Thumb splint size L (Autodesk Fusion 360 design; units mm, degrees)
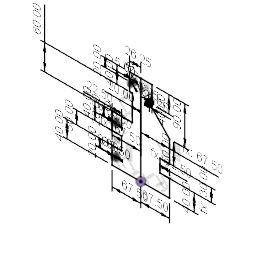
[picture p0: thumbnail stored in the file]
part number: 2025-11-24-13-59-10-673
sketch "Sketch1" plane through (0, 0, 0) normal (0, 1, 0) x axis (1, 0, 0)
  line L1 (-67.5, 0) -> (0, 0)
  line L2 (-67.5, -40) -> (-67.5, 0)
  line L3 (0, -210) -> (0, 0)
  line L4 (-45, -70) -> (-45, -40)
  line L5 (-67.5, -70) -> (-45, -70)
  line L6 (-67.5, -110) -> (-67.5, -70)
  line L7 (-20, -110) -> (-67.5, -110)
  line L8 (-20, -170) -> (-20, -110)
  line L9 (-26.25, -210) -> (-26.25, -170)
  line L10 (-26.25, -210) -> (0, -210)
  line L11 (26.25, -210) -> (0, -210)
  line L12 (26.25, -170) -> (26.25, -210)
  line L13 (67.5, -70) -> (67.5, -120)
  line L14 (67.5, 0) -> (0, 0)
  line L15 (67.5, -40) -> (67.5, 0)
  line L16 (-45, -40) -> (-67.5, -40)
  line L17 (45, -40) -> (67.5, -40)
  line L18 (45, -70) -> (45, -40)
  line L19 (67.5, -70) -> (45, -70)
  line L20 (-26.25, -170) -> (-20, -170)
  line L21 (67.5, -120) -> (20, -170)
  line L22 (20, -170) -> (26.25, -170)
  circle C1 centre (-59.5, -20) radius 1.75
  circle C2 centre (-59.5, -90) radius 1.75
  circle C3 centre (-21.25, -190) radius 1.75
  circle C4 centre (20, -170) radius 3.125
  point P1 (0, 0)
  point P2 (0, 0)
  point P6 (0, 0)
  point P20 (0, 0)
  point P3 (-67.5, 0)
  point P4 (-67.5, 0)
  point P28 (20, -170)
  point P29 (20, -170)
  point P5 (-67.5, -40)
  point P9 (-45, -40)
  point P10 (-45, -70)
  point P11 (-67.5, -70)
  point P12 (-67.5, -110)
  point P7 (0, -210)
  point P8 (-26.25, -210)
  point P16 (26.25, -210)
  point P17 (26.25, -170)
  point P15 (-26.25, -170)
  point P18 (67.5, -120)
  point P19 (67.5, -70)
  point P21 (67.5, 0)
  point P22 (67.5, -40)
  point P23 (45, -40)
  point P24 (45, -70)
  point P13 (-20, -110)
  point P14 (-20, -170)
  point P27 (-21.25, -190)
  point P26 (-59.5, -90)
  point P25 (-59.5, -20)
  coincident P1 P2
  coincident P1 P6
  perpendicular L1 L3
  vertical L4
  perpendicular L4 L5
  perpendicular L5 L6
  perpendicular L6 L7
  perpendicular L7 L8
  perpendicular L3 L10
  perpendicular L9 L10
  perpendicular L3 L11
  perpendicular L11 L12
  vertical L13
  coincident P1 P20
  perpendicular L3 L14
  perpendicular L14 L15
  perpendicular L2 L16
  perpendicular L15 L17
  perpendicular L18 L19
  perpendicular L13 L19
  coincident P3 P4
  perpendicular L1 L2
  perpendicular L8 L20
  perpendicular L4 L16
  perpendicular L12 L22
  coincident P28 P29
  dimension "d1" distance P2 P3 = 67.5 (= "( 135 / 2 ) * 1 mm")
  dimension "d2" distance P4 P5 = 40
  dimension "d4" distance P9 P10 = 30
  dimension "d7" distance P10 P11 = 22.5 (= "( ( 135 - 90 ) / 2 ) * 1 mm")
  dimension "d9" distance L3 P12 = 67.5 (= "d1")
  dimension "d10" distance P7 P8 = 26.25
  dimension "d11" distance P7 P16 = 26.25
  dimension "d12" distance P16 P17 = 40
  dimension "d13" distance P8 P15 = 40
  dimension "d14" distance L11 P18 = 90
  dimension "d15" distance L3 P18 = 67.5 (= "d1")
  dimension "d16" distance P18 P19 = 50
  dimension "d17" distance P20 P21 = 67.5
  dimension "d18" distance P21 P22 = 40
  dimension "d22" distance P23 P24 = 30 (= "d4")
  dimension "d23" distance L3 P13 = 20
  dimension "d44" distance P11 P12 = 40
  dimension "d45" distance P13 P14 = 60
  dimension "d46" diameter C1 = 3.5
  dimension "d47" diameter C2 = 3.5
  dimension "d48" diameter C3 = 3.5
  dimension "d49" distance L9 P27 = 5
  dimension "d50" distance L6 P26 = 8
  dimension "d51" distance L2 P25 = 8
  dimension "d52" distance L7 P26 = 20
  dimension "d53" distance L16 P25 = 20
  dimension "d54" distance L10 P27 = 20
  dimension "d67" distance P17 P28 = 6.25
  dimension "d74" distance P19 P24 = 22.5 (= "d7")
extrude "Extrude1" new body sketch "Sketch1" along normal blind 1.5
extrude "Extrude2" cut sketch "Sketch1" profile of C1 C2 C3 along normal blind 190.504
mirror "Mirror1" mirrorStitchTolerance 0.1
fillet "Fillet1" radius 10
fillet "Fillet2" radius 2
fillet "Fillet3" radius 10 10
fillet "Fillet4" radius 5
fillet "Fillet5" radius 25
fillet "Fillet7" radius 5 5
work_plane "WorkPlane1" AlongDistance -89.936
sketch "Sketch2" plane through (0, -89.936, 0) normal (0, 1, 0) x axis (1, 0, 0)
  line L1 (0, -210) -> (0, 0)
  circle C1 centre (-48, -13.48) radius 2
  circle C2 centre (-36, -13.48) radius 2
  circle C3 centre (-24, -13.48) radius 2
  circle C4 centre (-12, -13.48) radius 2
  circle C5 centre (0, -13.48) radius 2
  circle C6 centre (-48, -24.98) radius 2
  circle C7 centre (-36, -24.98) radius 2
  circle C8 centre (-24, -24.98) radius 2
  circle C9 centre (-12, -24.98) radius 2
  circle C10 centre (0, -24.98) radius 2
  circle C11 centre (-48, -36.48) radius 2
  circle C12 centre (-36, -36.48) radius 2
  circle C13 centre (-24, -36.48) radius 2
  circle C14 centre (-12, -36.48) radius 2
  circle C15 centre (0, -36.48) radius 2
  circle C16 centre (-48, -47.98) radius 2
  circle C17 centre (-36, -47.98) radius 2
  circle C18 centre (-24, -47.98) radius 2
  circle C19 centre (-12, -47.98) radius 2
  circle C20 centre (0, -47.98) radius 2
  circle C21 centre (12, -13.48) radius 2
  circle C22 centre (24, -13.48) radius 2
  circle C23 centre (36, -13.48) radius 2
  circle C24 centre (48, -13.48) radius 2
  circle C25 centre (12, -24.98) radius 2
  circle C26 centre (24, -24.98) radius 2
  circle C27 centre (36, -24.98) radius 2
  circle C28 centre (48, -24.98) radius 2
  circle C29 centre (12, -36.48) radius 2
  circle C30 centre (24, -36.48) radius 2
  circle C31 centre (36, -36.48) radius 2
  circle C32 centre (48, -36.48) radius 2
  circle C33 centre (12, -47.98) radius 2
  circle C34 centre (24, -47.98) radius 2
  circle C35 centre (36, -47.98) radius 2
  circle C36 centre (48, -47.98) radius 2
  circle C37 centre (-48, -59.48) radius 2
  circle C38 centre (-36, -59.48) radius 2
  circle C39 centre (-24, -59.48) radius 2
  circle C40 centre (-12, -59.48) radius 2
  circle C41 centre (0, -59.48) radius 2
  circle C42 centre (12, -59.48) radius 2
  circle C43 centre (24, -59.48) radius 2
  circle C44 centre (36, -59.48) radius 2
  circle C45 centre (48, -59.48) radius 2
  circle C46 centre (-48, -70.98) radius 2
  circle C47 centre (-36, -70.98) radius 2
  circle C48 centre (-24, -70.98) radius 2
  circle C49 centre (-12, -70.98) radius 2
  circle C50 centre (0, -70.98) radius 2
  circle C51 centre (12, -70.98) radius 2
  circle C52 centre (24, -70.98) radius 2
  circle C53 centre (36, -70.98) radius 2
  circle C54 centre (48, -70.98) radius 2
  circle C55 centre (-48, -82.48) radius 2
  circle C56 centre (-36, -82.48) radius 2
  circle C57 centre (-24, -82.48) radius 2
  circle C58 centre (-12, -82.48) radius 2
  circle C59 centre (0, -82.48) radius 2
  circle C60 centre (12, -82.48) radius 2
  circle C61 centre (24, -82.48) radius 2
  circle C62 centre (36, -82.48) radius 2
  circle C63 centre (48, -82.48) radius 2
  circle C64 centre (-48, -93.98) radius 2
  circle C65 centre (-36, -93.98) radius 2
  circle C66 centre (-24, -93.98) radius 2
  circle C67 centre (-12, -93.98) radius 2
  circle C68 centre (0, -93.98) radius 2
  circle C69 centre (12, -93.98) radius 2
  circle C70 centre (24, -93.98) radius 2
  circle C71 centre (36, -93.98) radius 2
  circle C72 centre (48, -93.98) radius 2
  circle C73 centre (-48, -105.48) radius 2
  circle C74 centre (-36, -105.48) radius 2
  circle C75 centre (-24, -105.48) radius 2
  circle C76 centre (-12, -105.48) radius 2
  circle C77 centre (0, -105.48) radius 2
  circle C78 centre (12, -105.48) radius 2
  circle C79 centre (24, -105.48) radius 2
  circle C80 centre (36, -105.48) radius 2
  circle C81 centre (48, -105.48) radius 2
  circle C82 centre (-48, -116.98) radius 2
  circle C83 centre (-36, -116.98) radius 2
  circle C84 centre (-24, -116.98) radius 2
  circle C85 centre (-12, -116.98) radius 2
  circle C86 centre (0, -116.98) radius 2
  circle C87 centre (12, -116.98) radius 2
  circle C88 centre (24, -116.98) radius 2
  circle C89 centre (36, -116.98) radius 2
  circle C90 centre (48, -116.98) radius 2
  circle C91 centre (-48, -128.48) radius 2
  circle C92 centre (-36, -128.48) radius 2
  circle C93 centre (-24, -128.48) radius 2
  circle C94 centre (-12, -128.48) radius 2
  circle C95 centre (0, -128.48) radius 2
  circle C96 centre (12, -128.48) radius 2
  circle C97 centre (24, -128.48) radius 2
  circle C98 centre (36, -128.48) radius 2
  circle C99 centre (48, -128.48) radius 2
  circle C100 centre (-48, -139.98) radius 2
  circle C101 centre (-36, -139.98) radius 2
  circle C102 centre (-24, -139.98) radius 2
  circle C103 centre (-12, -139.98) radius 2
  circle C104 centre (0, -139.98) radius 2
  circle C105 centre (12, -139.98) radius 2
  circle C106 centre (24, -139.98) radius 2
  circle C107 centre (36, -139.98) radius 2
  circle C108 centre (48, -139.98) radius 2
  circle C109 centre (-48, -151.48) radius 2
  circle C110 centre (-36, -151.48) radius 2
  circle C111 centre (-24, -151.48) radius 2
  circle C112 centre (-12, -151.48) radius 2
  circle C113 centre (0, -151.48) radius 2
  circle C114 centre (12, -151.48) radius 2
  circle C115 centre (24, -151.48) radius 2
  circle C116 centre (36, -151.48) radius 2
  circle C117 centre (48, -151.48) radius 2
  circle C118 centre (-48, -162.98) radius 2
  circle C119 centre (-36, -162.98) radius 2
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  point P6 (0, -13.48)
  coincident P6 L1
  dimension "d60" diameter C1 = 4
  dimension "d63" R-Pattern1-uDistance = 12
  dimension "d64" R-Pattern1-vDistance = -11.5
extrude "Extrude3" cut sketch "Sketch2" along normal blind 321.2595
fillet "Fillet8" radius 15 5 5
sketch "Sketch3" plane through (0, 0, 0) normal (0, -1, 0) x axis (1, 0, 0)
  line L1 (26.25, 200) -> (26.25, 171.5216)
  line L2 (-16.25, 210) -> (16.25, 210)
  line L3 (-26.25, 174.2702) -> (-26.25, 200)
  line L4 (-20, 135) -> (-20, 165)
  line L5 (-62.5, 110) -> (-45, 110)
  line L6 (-67.5, 75) -> (-67.5, 105)
  line L7 (-55, 70) -> (-62.5, 70)
  line L8 (-45, 50) -> (-45, 60)
  line L9 (-62.5, 40) -> (-55, 40)
  line L10 (-67.5, 2) -> (-67.5, 35)
  line L11 (65.5, 0) -> (-65.5, 0)
  line L12 (67.5, 35) -> (67.5, 2)
  line L13 (55, 40) -> (62.5, 40)
  line L14 (45, 60) -> (45, 50)
  line L15 (62.5, 70) -> (55, 70)
  line L16 (67.5, 114.0109) -> (67.5, 75)
  line L17 (26.3934, 163.2701) -> (63.375, 124.3421)
  arc A1 centre (21.25, 171.5216) radius 5 clockwise from (26.25, 171.5216) to (25.6342, 169.1177)
  arc A2 centre (16.25, 200) radius 10 clockwise from (16.25, 210) to (26.25, 200)
  arc A3 centre (-16.25, 200) radius 10 clockwise from (-26.25, 200) to (-16.25, 210)
  arc A4 centre (-21.25, 174.2702) radius 5 clockwise from (-23.125, 169.6351) to (-26.25, 174.2702)
  arc A5 centre (-25, 165) radius 5 clockwise from (-23.125, 169.6351) to (-20, 165)
  arc A6 centre (-45, 135) radius 25 clockwise from (-20, 135) to (-45, 110)
  arc A7 centre (-62.5, 105) radius 5 clockwise from (-67.5, 105) to (-62.5, 110)
  arc A8 centre (-62.5, 75) radius 5 clockwise from (-62.5, 70) to (-67.5, 75)
  arc A9 centre (-55, 60) radius 10 clockwise from (-55, 70) to (-45, 60)
  arc A10 centre (-55, 50) radius 10 clockwise from (-45, 50) to (-55, 40)
  arc A11 centre (-62.5, 35) radius 5 clockwise from (-67.5, 35) to (-62.5, 40)
  arc A12 centre (-65.5, 2) radius 2 clockwise from (-65.5, 0) to (-67.5, 2)
  arc A13 centre (65.5, 2) radius 2 clockwise from (67.5, 2) to (65.5, 0)
  arc A14 centre (62.5, 35) radius 5 clockwise from (62.5, 40) to (67.5, 35)
  arc A15 centre (55, 50) radius 10 clockwise from (55, 40) to (45, 50)
  arc A16 centre (55, 60) radius 10 clockwise from (45, 60) to (55, 70)
  arc A17 centre (62.5, 75) radius 5 clockwise from (67.5, 75) to (62.5, 70)
  arc A18 centre (52.5, 114.0109) radius 15 clockwise from (63.375, 124.3421) to (67.5, 114.0109)
  arc A19 centre (30.0184, 166.7138) radius 5 clockwise from (26.3934, 163.2701) to (25.6342, 169.1177)
  circle C1 centre (-59.5, 20) radius 1.75
  circle C2 centre (-59.5, 90) radius 1.75
  circle C3 centre (-21.25, 190) radius 1.75
  circle C4 centre (59.5, 20) radius 1.75
  circle C5 centre (59.5, 90) radius 1.75
  circle C6 centre (21.25, 190) radius 1.75
  circle C7 centre (36, 36.48) radius 2
  circle C8 centre (12, 197.48) radius 2
  circle C9 centre (-12, 151.48) radius 2
  circle C10 centre (-36, 47.98) radius 2
  circle C11 centre (-12, 36.48) radius 2
  circle C12 centre (0, 151.48) radius 2
  circle C13 centre (-12, 47.98) radius 2
  circle C14 centre (-12, 59.48) radius 2
  circle C15 centre (12, 185.98) radius 2
  circle C16 centre (36, 24.98) radius 2
  circle C17 centre (12, 151.48) radius 2
  circle C18 centre (24, 151.48) radius 2
  circle C19 centre (24, 139.98) radius 2
  circle C20 centre (12, 139.98) radius 2
  circle C21 centre (24, 128.48) radius 2
  circle C22 centre (-48, 24.98) radius 2
  circle C23 centre (0, 185.98) radius 2
  circle C24 centre (36, 116.98) radius 2
  circle C25 centre (12, 116.98) radius 2
  circle C26 centre (-12, 116.98) radius 2
  circle C27 centre (-12, 174.48) radius 2
  circle C28 centre (-12, 105.48) radius 2
  circle C29 centre (-12, 24.98) radius 2
  circle C30 centre (-24, 24.98) radius 2
  circle C31 centre (-12, 128.48) radius 2
  circle C32 centre (24, 36.48) radius 2
  circle C33 centre (12, 47.98) radius 2
  circle C34 centre (48, 105.48) radius 2
  circle C35 centre (0, 116.98) radius 2
  circle C36 centre (24, 70.98) radius 2
  circle C37 centre (12, 82.48) radius 2
  circle C38 centre (-24, 93.98) radius 2
  circle C39 centre (24, 59.48) radius 2
  circle C40 centre (0, 82.48) radius 2
  circle C41 centre (0, 93.98) radius 2
  circle C42 centre (-36, 70.98) radius 2
  circle C43 centre (-36, 82.48) radius 2
  circle C44 centre (-48, 82.48) radius 2
  circle C45 centre (36, 128.48) radius 2
  circle C46 centre (0, 36.48) radius 2
  circle C47 centre (0, 47.98) radius 2
  circle C48 centre (-36, 93.98) radius 2
  circle C49 centre (36, 93.98) radius 2
  circle C50 centre (48, 93.98) radius 2
  circle C51 centre (12, 105.48) radius 2
  circle C52 centre (24, 93.98) radius 2
  circle C53 centre (36, 13.48) radius 2
  circle C54 centre (12, 174.48) radius 2
  circle C55 centre (48, 13.48) radius 2
  circle C56 centre (12, 24.98) radius 2
  circle C57 centre (-12, 197.48) radius 2
  circle C58 centre (36, 47.98) radius 2
  circle C59 centre (36, 70.98) radius 2
  circle C60 centre (-24, 105.48) radius 2
  circle C61 centre (12, 93.98) radius 2
  circle C62 centre (-24, 36.48) radius 2
  circle C63 centre (0, 139.98) radius 2
  circle C64 centre (24, 13.48) radius 2
  circle C65 centre (12, 36.48) radius 2
  circle C66 centre (48, 24.98) radius 2
  circle C67 centre (-36, 59.48) radius 2
  circle C68 centre (-48, 93.98) radius 2
  circle C69 centre (-12, 82.48) radius 2
  circle C70 centre (-12, 185.98) radius 2
  circle C71 centre (12, 128.48) radius 2
  circle C72 centre (-12, 13.48) radius 2
  circle C73 centre (-24, 70.98) radius 2
  circle C74 centre (-12, 70.98) radius 2
  circle C75 centre (0, 105.48) radius 2
  circle C76 centre (0, 162.98) radius 2
  circle C77 centre (-36, 13.48) radius 2
  circle C78 centre (24, 47.98) radius 2
  circle C79 centre (12, 13.48) radius 2
  circle C80 centre (0, 128.48) radius 2
  circle C81 centre (12, 162.98) radius 2
  circle C82 centre (0, 59.48) radius 2
  circle C83 centre (36, 105.48) radius 2
  circle C84 centre (-48, 13.48) radius 2
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  point P165 (25.06, 166.0701)
  midpoint A19 P165
extrude "Extrude4" cut sketch "Sketch3" against normal blind 34.699
fillet "Fillet9" radius 5 5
